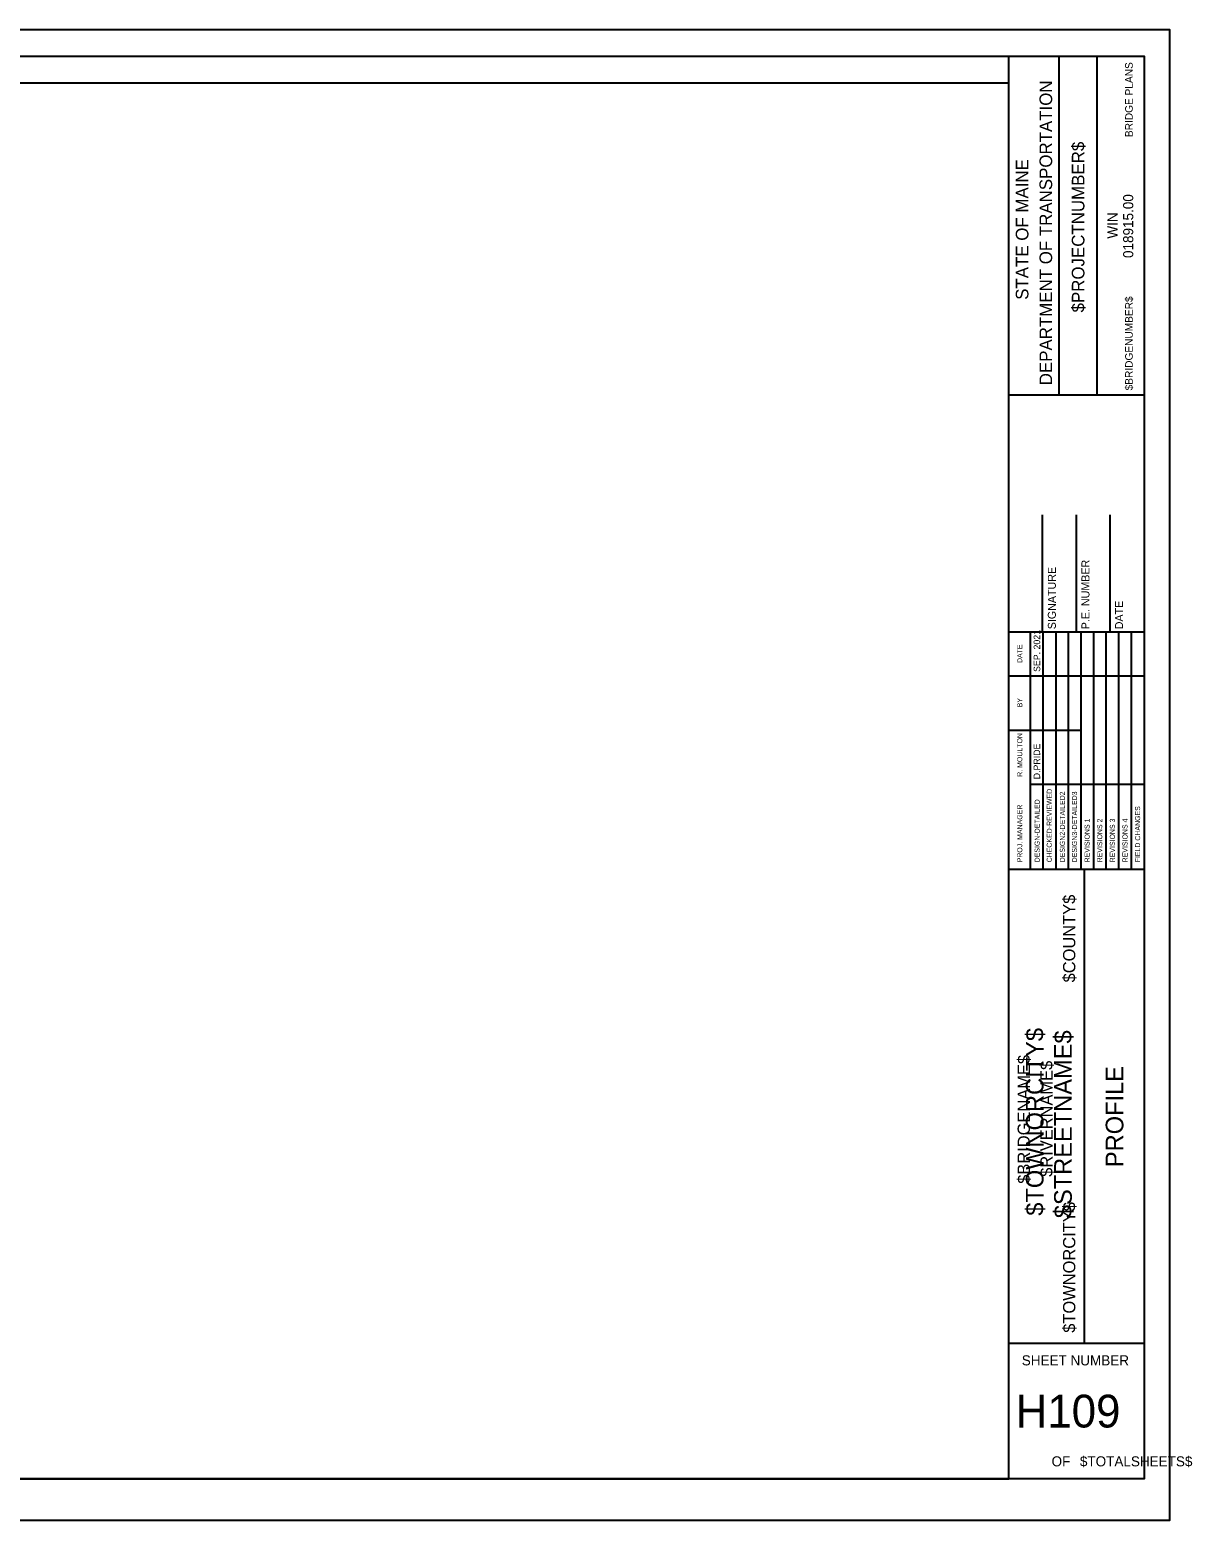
# Model space of a CAD drawing. Extents: x 40264 to 41122, y 9985 to 10535.
# Drawn here: x 40693 to 41122, y 9985 to 10535 of the extents above; entities that cross this region are included whole.
import ezdxf

# ---------------------------------------------------------------- set-up
doc = ezdxf.new("R2010")
doc.units = 0
for name, color, linetype in [('BORDER', 7, 'Continuous'), ('BRIDGE_TITLE', 7, 'Continuous'), ('CLIPS', 7, 'Continuous'), ('HIGHWAY_TITLE', 7, 'Continuous'), ('PLOT BOUNDARY', 7, 'Continuous')]:
    doc.layers.add(name, color=color, linetype=linetype)

msp = doc.modelspace()

# ---------------------------------------------------------------- linework, layer by layer
at = {"layer": 'BORDER'}
for p, q in [((41054.38, 10000), (41054.38, 10525)), ((41073.03, 10399.99), (41073.03, 10524.99)), ((41087, 10399.99), (41087, 10524.99)), ((41054.39, 10399.97), (41104.38, 10399.97)), ((41066.88, 10312.51), (41066.88, 10355.75)), ((41079.38, 10312.51), (41079.38, 10355.75)), ((41091.88, 10312.51), (41091.88, 10355.75)), ((41054.38, 10312.51), (41104.38, 10312.51)), ((41054.38, 10225.01), (41104.38, 10225.01)), ((41082.34, 10050.01), (41082.34, 10225.01)), ((41054.38, 10050.01), (41104.38, 10050.01))]:
    msp.add_line(p, q, dxfattribs=at)
msp.add_lwpolyline([(40304.38, 10525), (41104.38, 10525), (41104.38, 10000), (40304.38, 10000)], close=True, dxfattribs=at)
for points in [[(41062.46, 10296.26), (41062.46, 10312.51)], [(41067.12, 10225.03), (41067.12, 10312.51)], [(41071.78, 10312.51), (41071.78, 10225.03)], [(41076.44, 10225.03), (41076.44, 10312.51)], [(41081.1, 10225.03), (41081.1, 10312.51)], [(41085.75, 10225.03), (41085.75, 10312.51)], [(41090.41, 10225.03), (41090.41, 10312.51)], [(41095.07, 10225.03), (41095.07, 10312.51)], [(41099.73, 10225.03), (41099.73, 10312.51)], [(41062.46, 10225.03), (41062.46, 10308.98)], [(41054.38, 10296.26), (41104.38, 10296.26)], [(41054.38, 10276.26), (41062.46, 10276.26)], [(41062.46, 10276.26), (41081.09, 10276.26)], [(41062.46, 10256.26), (41104.38, 10256.26)]]:
    msp.add_lwpolyline(points, dxfattribs=at)
at = {"layer": 'CLIPS'}
msp.add_lwpolyline([(40304.38, 10000), (41054.38, 10000), (41054.38, 10515), (40304.38, 10515)], close=True, dxfattribs=at)
at = {"layer": 'PLOT BOUNDARY'}
msp.add_lwpolyline([(40263.92, 9984.7), (41113.92, 9984.7), (41113.92, 10534.7), (40263.92, 10534.7)], close=True, dxfattribs=at)

# ---------------------------------------------------------------- texts
at = {"layer": 'BORDER'}
for s, height, rotation, p in [('DEPARTMENT OF TRANSPORTATION', 4.6588, 90, (41070.42, 10403.53)), ('$PROJECTNUMBER$', 4.6588, 90, (41082.34, 10430.4)), ('STATE OF MAINE', 4.6588, 90, (41061.66, 10435.06)), ('018915.00', 3.726, 90, (41100.36, 10450.49)), ('WIN', 3.726, 90, (41094.57, 10457.65)), ('SIGNATURE', 2.953, 90, (41071.79, 10313.48)), ('P.E. NUMBER', 2.9528, 90, (41084.19, 10313.48)), ('DATE', 2.953, 90, (41096.59, 10313.48)), ('SEP. 2021', 2.423, 90, (41066, 10297.74)), ('DATE', 1.857, 90, (41059.4, 10301.04)), ('BY', 1.857, 90, (41059.4, 10284.69)), ('R. MOULTON', 1.864, 90, (41059.4, 10259.03)), ('D.PRIDE', 2.423, 90, (41066, 10258.13)), ('CHECKED-REVIEWED', 1.8637, 90, (41070.29, 10227.46)), ('DESIGN2-DETAILED2', 1.8637, 90, (41075.13, 10227.46)), ('DESIGN3-DETAILED3', 1.8637, 90, (41079.6, 10227.46)), ('PROJ. MANAGER', 1.8637, 90, (41059.4, 10227.46)), ('DESIGN-DETAILED', 1.8637, 90, (41065.82, 10227.46)), ('FIELD CHANGES', 1.8637, 90, (41102.9, 10227.46)), ('REVISIONS 1', 1.8637, 90, (41084.26, 10227.46)), ('REVISIONS 2', 1.8637, 90, (41088.92, 10227.46)), ('REVISIONS 3', 1.8637, 90, (41093.58, 10227.46)), ('REVISIONS 4', 1.8637, 90, (41098.24, 10227.46)), ('PROFILE', 6.521, 90, (41096.71, 10115)), ('SHEET NUMBER', 3.7264, 360, (41059.21, 10041.83)), ('H109', 12.097, 360, (41056.96, 10018.91)), ('OF', 3.726, 360, (41070.22, 10004.56)), ('$TOTALSHEETS$', 3.7264, 360, (41080.67, 10004.56))]:
    msp.add_text(s, height=height, rotation=rotation, dxfattribs=at).set_placement(p)
at = {"layer": 'BRIDGE_TITLE'}
for s, height, p in [('BRIDGE PLANS', 2.795, (41100.17, 10495.12)), ('$BRIDGENUMBER$', 2.795, (41100.17, 10401.65)), ('$COUNTY$', 4.536, (41078.98, 10183.17)), ('$BRIDGENAME$', 4.5358, (41062.21, 10108.86)), ('$RIVERNAME$', 4.5358, (41070.6, 10111.43)), ('$TOWNORCITY$', 4.5358, (41078.98, 10053.88))]:
    msp.add_text(s, height=height, rotation=90, dxfattribs=at).set_placement(p)
at = {"layer": 'HIGHWAY_TITLE'}
for s, p in [('$TOWNORCITY$', (41067.24, 10097.06)), ('$STREETNAME$', (41077.68, 10096.16))]:
    msp.add_text(s, height=6.5214, rotation=90, dxfattribs=at).set_placement(p)

doc.saveas('drawing.dxf')
